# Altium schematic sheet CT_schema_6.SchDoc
size 284 x 211 mm
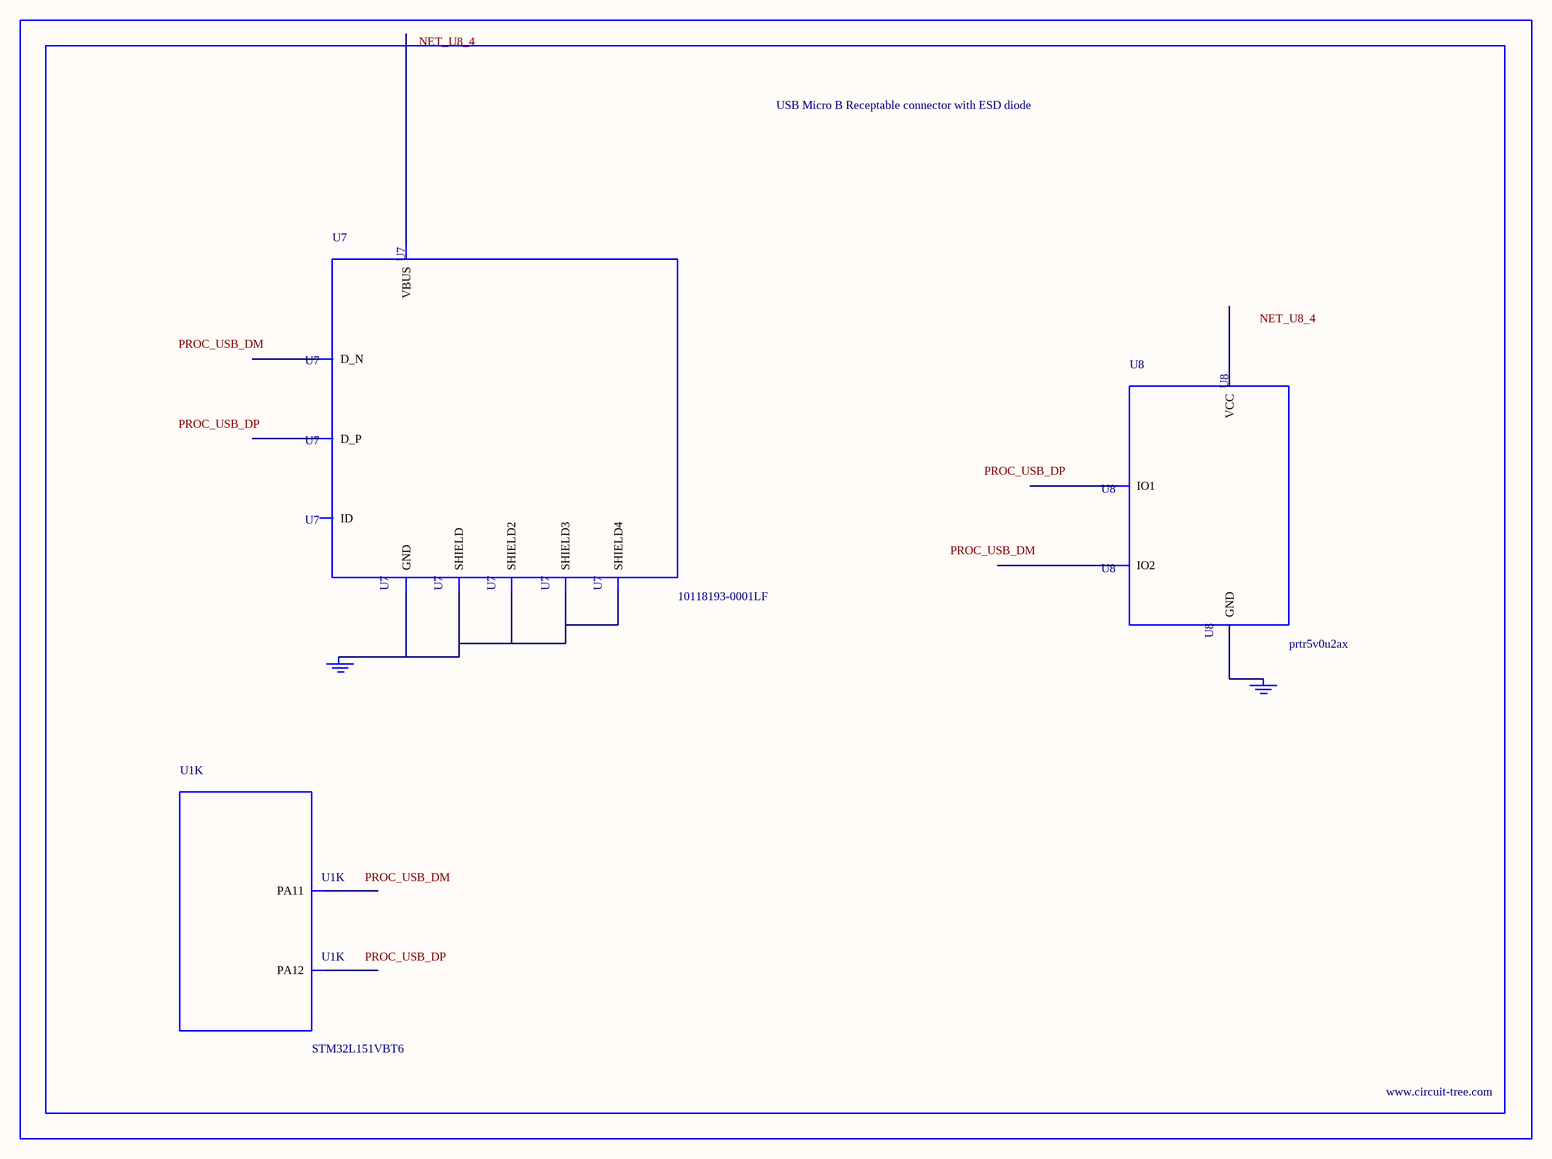
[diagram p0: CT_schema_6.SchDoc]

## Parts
BORDER5  (no value)
GND_INSTANCE_5_0  (no value)
GND_INSTANCE_5_1  (no value)
U1  STM32L151VBT6  [LQFP100]  (part K of 11)
U7  10118193-0001LF  [FCI_10118193-0001LF]
U8  prtr5v0u2ax  [SOT143B]

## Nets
NetGND_INSTANCE_5_0_0: GND_INSTANCE_5_0.0(GND) U7.5(GND) U7.6(SHIELD) U7.7(SHIELD2) U7.8(SHIELD3) U7.9(SHIELD4)
NetGND_INSTANCE_5_1_0: GND_INSTANCE_5_1.0(GND) U8.1(GND)

Not connected (* = marked no-connect by the designer): U1 70(PA11) 71(PA12); U7 1(VBUS) 2(D_N) 3(D_P) 4(ID); U8 2(IO1) 3(IO2) 4(VCC)

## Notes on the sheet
- Labels drawn without touching a wire or pin: NET_U8_4, PROC_USB_DM, PROC_USB_DP

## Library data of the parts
BORDER5 = BORDER_PAGE5
GND_INSTANCE_5_0 GND_INSTANCE_5_1 = GND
